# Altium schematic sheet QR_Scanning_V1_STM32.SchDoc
size 381 x 241 mm; SheetNumber: 1; SheetTotal: 3
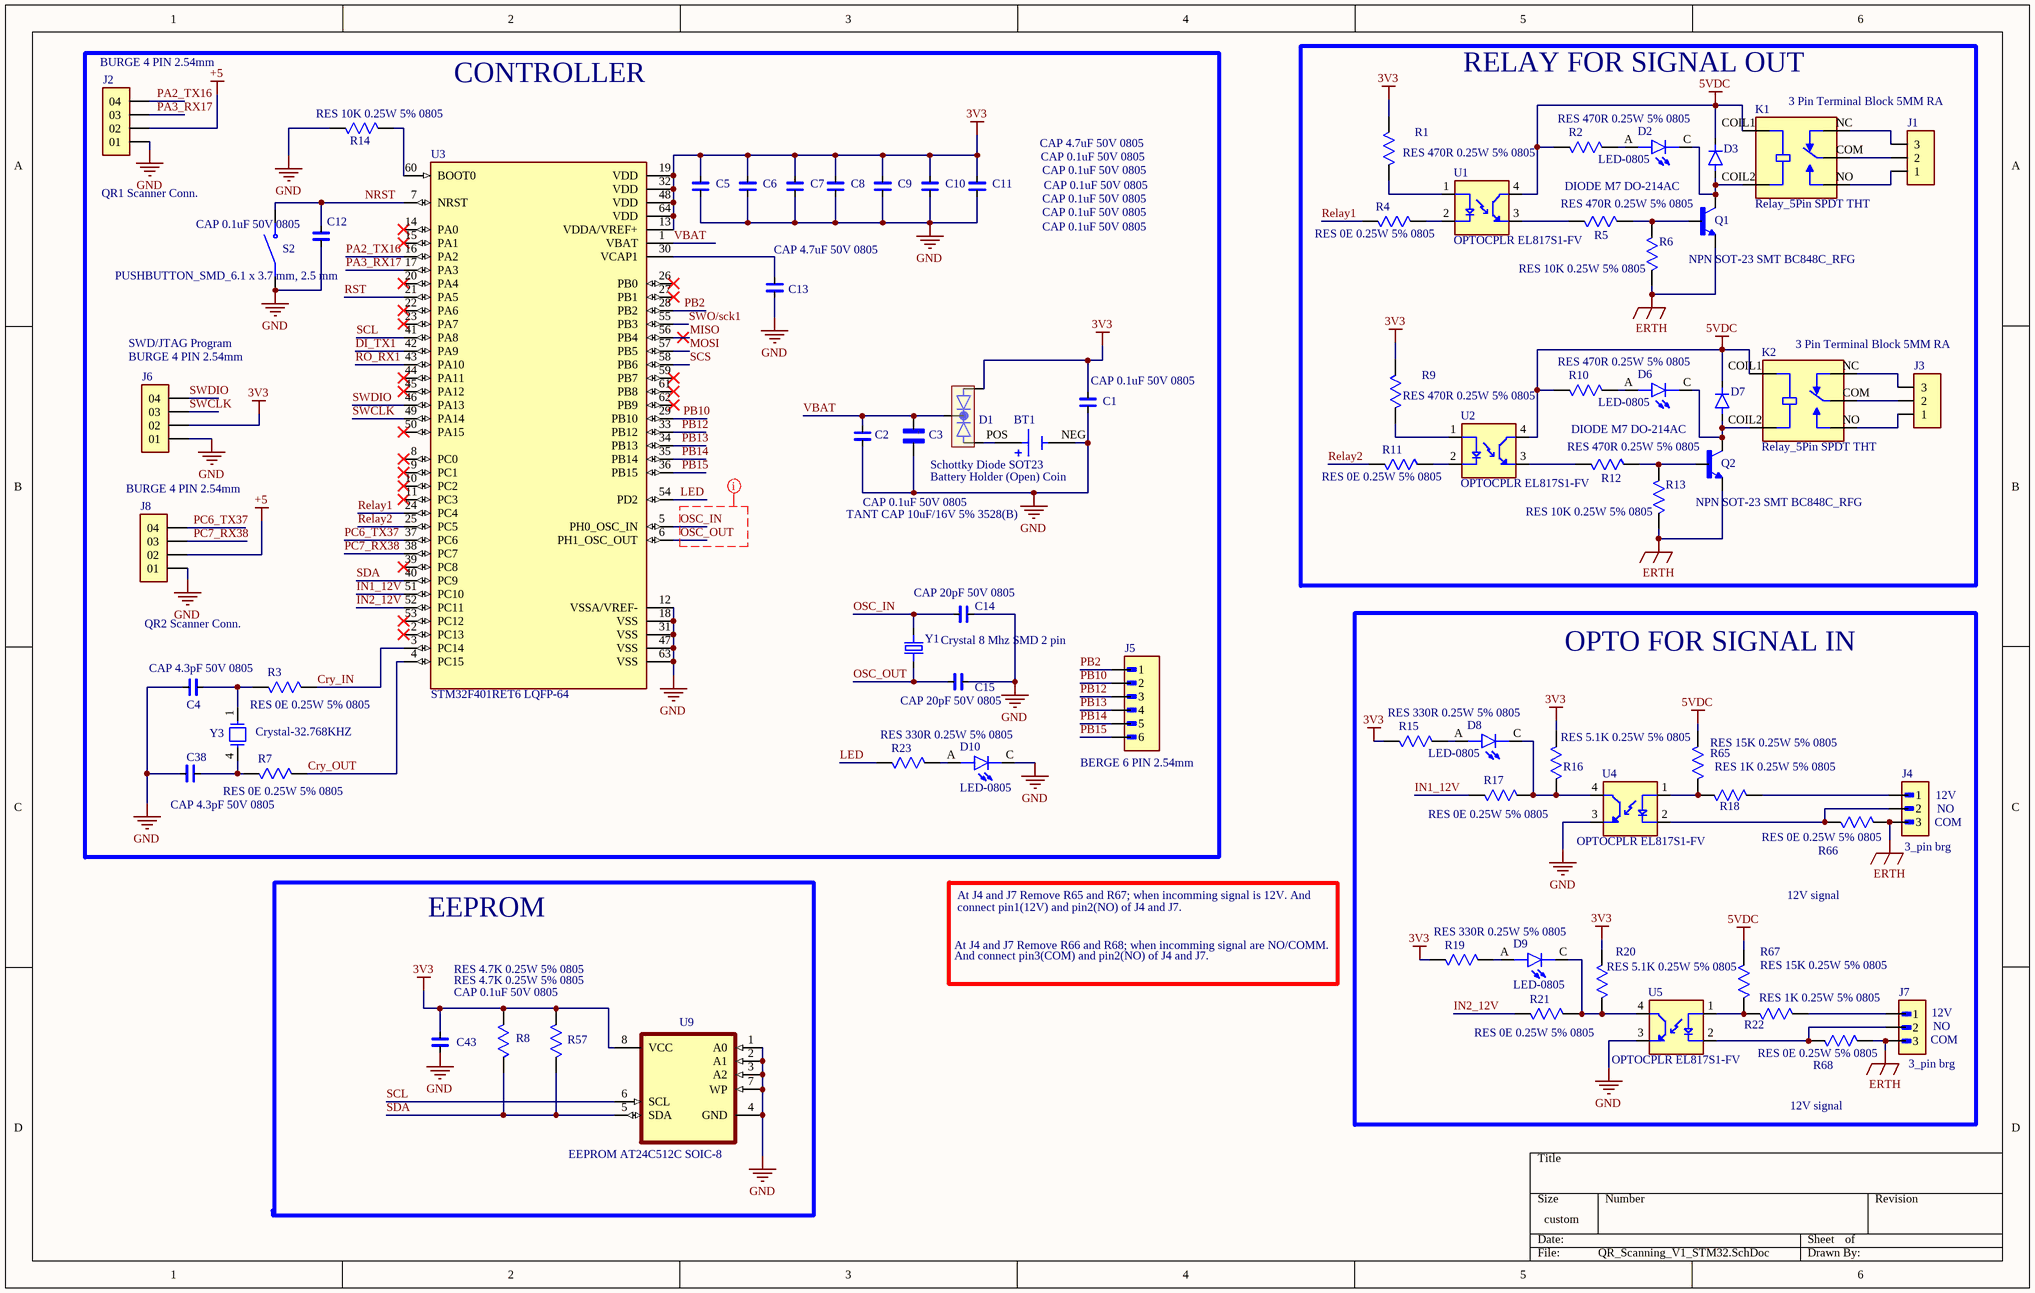
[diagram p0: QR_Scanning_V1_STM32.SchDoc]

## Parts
BT1  Battery Holder (Open) Coin  [Battery Holder (Open) Coin]
C1  CAP 0.1uF 50V 0805  [CAP CER 0.1uF/50V 5%]
C2  CAP 0.1uF 50V 0805  [CAP CER 0.1uF/50V 5%]
C3  TANT CAP 10uF/16V 5% 3528(B)  [TANT CAP 3528(B)]
C4  CAP 4.3pF 50V 0805  [CAP CER 0.1uF/50V 5%]
C5  CAP 0.1uF 50V 0805  [CAP CER 0.1uF/50V 5%]
C6  CAP 0.1uF 50V 0805  [CAP CER 0.1uF/50V 5%]
C7  CAP 0.1uF 50V 0805  [CAP CER 0.1uF/50V 5%]
C8  CAP 0.1uF 50V 0805  [CAP CER 0.1uF/50V 5%]
C9  CAP 0.1uF 50V 0805  [CAP CER 0.1uF/50V 5%]
C10  CAP 0.1uF 50V 0805  [CAP CER 0.1uF/50V 5%]
C11  CAP 4.7uF 50V 0805  [CAP CER 0.1uF/50V 5%]
C12  CAP 0.1uF 50V 0805  [CAP CER 0.1uF/50V 5%]
C13  CAP 4.7uF 50V 0805  [CAP CER 0.1uF/50V 5%]
C14  CAP 20pF 50V 0805  [CAP CER 0.1uF/50V 5%]
C15  CAP 20pF 50V 0805  [CAP CER 0.1uF/50V 5%]
C38  CAP 4.3pF 50V 0805  [CAP CER 0.1uF/50V 5%]
C43  CAP 0.1uF 50V 0805  [CAP CER 0.1uF/50V 5%]
D1  Schottky Diode SOT23  [Schottky Diode SOT23 BAT54C]
D2  LED-0805  [LED-0805]
D3  DIODE M7 DO-214AC  [DIODE M7 DO-214AC]
D6  LED-0805  [LED-0805]
D7  DIODE M7 DO-214AC  [DIODE M7 DO-214AC]
D8  LED-0805  [LED-0805]
D9  LED-0805  [LED-0805]
D10  LED-0805  [LED-0805]
J1  3 Pin Terminal Block 5MM RA  [3 Pin Terminal Block 5MM RA]
J2  BURGE 4 PIN 2.54mm  [BURGE 4 PIN 2.54mm]
J3  3 Pin Terminal Block 5MM RA  [3 Pin Terminal Block 5MM RA]
J4  3_pin brg  [3_pin brg]
J5  BERGE 6 PIN 2.54mm  [BERGE 6 PIN 2.54mm]
J6  BURGE 4 PIN 2.54mm  [BURGE 4 PIN 2.54mm]
J7  3_pin brg  [3_pin brg]
J8  BURGE 4 PIN 2.54mm  [BURGE 4 PIN 2.54mm]
K1  Relay_5Pin SPDT THT  [Relay_5Pin SPDT THT]
K2  Relay_5Pin SPDT THT  [Relay_5Pin SPDT THT]
Q1  NPN SOT-23 SMT BC848C_RFG  [NPN SOT-23 SMT BC848C_RFG]
Q2  NPN SOT-23 SMT BC848C_RFG  [NPN SOT-23 SMT BC848C_RFG]
R1  RES 470R 0.25W 5% 0805  [RES 0805 10K/0.25W 5%]
R2  RES 470R 0.25W 5% 0805  [RES 0805 10K/0.25W 5%]
R3  RES 0E 0.25W 5% 0805  [RES 0805 10K/0.25W 5%]
R4  RES 0E 0.25W 5% 0805  [RES 0805 10K/0.25W 5%]
R5  RES 470R 0.25W 5% 0805  [RES 0805 10K/0.25W 5%]
R6  RES 10K 0.25W 5% 0805  [RES 0805 10K/0.25W 5%]
R7  RES 0E 0.25W 5% 0805  [RES 0805 10K/0.25W 5%]
R8  RES 4.7K 0.25W 5% 0805  [RES 0805 10K/0.25W 5%]
R9  RES 470R 0.25W 5% 0805  [RES 0805 10K/0.25W 5%]
R10  RES 470R 0.25W 5% 0805  [RES 0805 10K/0.25W 5%]
R11  RES 0E 0.25W 5% 0805  [RES 0805 10K/0.25W 5%]
R12  RES 470R 0.25W 5% 0805  [RES 0805 10K/0.25W 5%]
R13  RES 10K 0.25W 5% 0805  [RES 0805 10K/0.25W 5%]
R14  RES 10K 0.25W 5% 0805  [RES 0805 10K/0.25W 5%]
R15  RES 330R 0.25W 5% 0805  [RES 0805 10K/0.25W 5%]
R16  RES 5.1K 0.25W 5% 0805  [RES 0805 10K/0.25W 5%]
R17  RES 0E 0.25W 5% 0805  [RES 0805 10K/0.25W 5%]
R18  RES 1K 0.25W 5% 0805  [RES 0805 10K/0.25W 5%]
R19  RES 330R 0.25W 5% 0805  [RES 0805 10K/0.25W 5%]
R20  RES 5.1K 0.25W 5% 0805  [RES 0805 10K/0.25W 5%]
R21  RES 0E 0.25W 5% 0805  [RES 0805 10K/0.25W 5%]
R22  RES 1K 0.25W 5% 0805  [RES 0805 10K/0.25W 5%]
R23  RES 330R 0.25W 5% 0805  [RES 0805 10K/0.25W 5%]
R57  RES 4.7K 0.25W 5% 0805  [RES 0805 10K/0.25W 5%]
R65  RES 15K 0.25W 5% 0805  [RES 0805 10K/0.25W 5%]
R66  RES 0E 0.25W 5% 0805  [RES 0805 10K/0.25W 5%]
R67  RES 15K 0.25W 5% 0805  [RES 0805 10K/0.25W 5%]
R68  RES 0E 0.25W 5% 0805  [RES 0805 10K/0.25W 5%]
S2  PUSHBUTTON_SMD_6.1 x 3.7 mm, 2.5 mm  [PUSHBUTTON_SMD_6.1 x 3.7 mm, 2.5 mm]
U1  OPTOCPLR EL817S1-FV  [OPTOCPLR EL817S1-FV]
U2  OPTOCPLR EL817S1-FV  [OPTOCPLR EL817S1-FV]
U3  STM32F401RET6 LQFP-64  [STM32F401RE Cortex-M4]
U4  OPTOCPLR EL817S1-FV  [OPTOCPLR EL817S1-FV]
U5  OPTOCPLR EL817S1-FV  [OPTOCPLR EL817S1-FV]
U9  EEPROM AT24C512C SOIC-8  [EEPROM AT24C512C SOIC-8]
Y1  Crystal 8 Mhz SMD 2 pin  [Crystal 16 Mhz SMD 2 pin]
Y3  Crystal-32.768KHZ  [Crystal-32.768KHZ]

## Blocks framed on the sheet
CONTROLLER: BT1 C1-C15 C38 D1 D10 J2 J5 J6 J8 R3 R7 R14 R23 S2 U3 Y1 Y3
RELAY FOR SIGNAL OUT: D2 D3 D6 D7 J1 J3 K1 K2 Q1 Q2 R1 R2 R4-R6 R9-R13 U1 U2
OPTO FOR SIGNAL IN: D8 D9 J4 J7 R15-R22 R65-R68 U4 U5

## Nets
3V3: C1.2 C5.2 C6.2 C7.2 C8.2 C9.2 C10.2 C11.2 C43.2 D1.1(A1) J6.02 R1.2 R8.2 R9.2 R15.2 R16.1 R19.2 R20.1 R57.2 U3.13(VDDA/VREF+) U3.19(VDD) U3.32(VDD) U3.48(VDD) U3.64(VDD) U9.8(VCC)
5VDC: D3.C(K) D7.C(K) K1.COIL1 K2.COIL1 R2.2 R10.2 R65.1 R67.1 U1.4(CT) U2.4(CT)
+5: J2.02 J8.02
ERTH: J4.3 J7.3 Q1.2(E) Q2.2(E) R6.1 R13.1 R66.1 R68.1
GND: BT1.NEG C1.1 C2.1 C3.2 C4.2 C5.1 C6.1 C7.1 C8.1 C9.1 C10.1 C11.1 C12.1 C13.1 C14.2 C15.2 C38.2 C43.1 D10.C J2.01 J6.01 J8.01 R14.1 S2.1 U3.12(VSSA/VREF-) U3.18(VSS) U3.31(VSS) U3.47(VSS) U3.63(VSS) U4.3(ET) U5.3(ET) U9.1(A0) U9.2(A1) U9.3(A2) U9.4(GND) U9.7(WP)
Cry_IN: R3.1 U3.3(PC14)
Cry_OUT: R7.1 U3.4(PC15)
DI_TX1: U3.42(PA9)
IN1_12V: R17.2 U3.51(PC10)
IN2_12V: R21.2 U3.52(PC11)
LED: R23.2 U3.54(PD2)
MISO: U3.56(PB4)
MOSI: U3.57(PB5)
NRST: C12.2 S2.2 U3.7(NRST)
OSC_IN: C14.1 U3.5(PH0_OSC_IN) Y1.2
OSC_OUT: C15.1 U3.6(PH1_OSC_OUT) Y1.1
PA2_TX16: J2.04 U3.16(PA2)
PA3_RX17: J2.03 U3.17(PA3)
PB2: J5.1 U3.28(PB2)
PB10: J5.2 U3.29(PB10)
PB12: J5.3 U3.33(PB12)
PB13: J5.4 U3.34(PB13)
PB14: J5.5 U3.35(PB14)
PB15: J5.6 U3.36(PB15)
PC6_TX37: J8.04 U3.37(PC6)
PC7_RX38: J8.03 U3.38(PC7)
Relay1: R4.2 U3.24(PC4)
Relay2: R11.2 U3.25(PC5)
RO_RX1: U3.43(PA10)
RST: U3.21(PA5)
SCL: U3.41(PA8) U9.6(SCL)
SCS: U3.58(PB6)
SDA: R8.1 R57.1 U3.40(PC9) U9.5(SDA)
SWCLK: J6.03 U3.49(PA14)
SWDIO: J6.04 U3.46(PA13)
SWO/sck1: U3.55(PB3)
VBAT: C2.2 C3.1 D1.3(C) U3.1(VBAT)
NetBT1_POS: BT1.POS D1.2(A2)
NetC4_1: C4.1 R3.2 Y3.1
NetC13_2: C13.2 U3.30(VCAP1)
NetC38_1: C38.1 R7.2 Y3.4
NetD2_A: D2.A R2.1
NetD2_C: D2.C D3.A K1.COIL2 Q1.3(C)
NetD6_A: D6.A R10.1
NetD6_C: D6.C D7.A K2.COIL2 Q2.3(C)
NetD8_A: D8.A R15.1
NetD8_C: D8.C R16.2 R17.1 U4.4(CT)
NetD9_A: D9.A R19.1
NetD9_C: D9.C R20.2 R21.1 U5.4(CT)
NetD10_A: D10.A R23.1
NetJ1_1: J1.1 K1.NO
NetJ1_2: J1.2 K1.COM
NetJ1_3: J1.3 K1.NC
NetJ3_1: J3.1 K2.NO
NetJ3_2: J3.2 K2.COM
NetJ3_3: J3.3 K2.NC
NetJ4_1: J4.1 R18.1
NetJ4_2: J4.2 R66.2 U4.2(C)
NetJ7_1: J7.1 R22.1
NetJ7_2: J7.2 R68.2 U5.2(C)
NetQ1_1: Q1.1(B) R5.2 R6.2
NetQ2_1: Q2.1(B) R12.2 R13.2
NetR1_1: R1.1 U1.1(A)
NetR4_1: R4.1 U1.2(C)
NetR5_1: R5.1 U1.3(ET)
NetR9_1: R9.1 U2.1(A)
NetR11_1: R11.1 U2.2(C)
NetR12_1: R12.1 U2.3(ET)
NetR14_2: R14.2 U3.60(BOOT0)
NetR18_2: R18.2 R65.2 U4.1(A)
NetR22_2: R22.2 R67.2 U5.1(A)

Not connected (* = marked no-connect by the designer): U3 2(PC13)* 8(PC0)* 9(PC1)* 10(PC2)* 11(PC3)* 14(PA0)* 15(PA1)* 20(PA4)* 22(PA6)* 23(PA7)* 26(PB0)* 27(PB1)* 39(PC8)* 44(PA11)* 45(PA12)* 50(PA15)* 53(PC12)* 59(PB7)* 61(PB8)* 62(PB9)*

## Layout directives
net class Single_50 ohm: OSC_IN, OSC_OUT

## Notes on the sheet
- (near J2) QR1 Scanner Conn.
- (near J6) SWD/JTAG Program
- QR2 Scanner Conn.
- (near J4) COM
- (near J4) 12V
- (near J4) NO
- At J4 and J7 Remove R65 and R67; when incomming signal is 12V. And
- connect pin1(12V) and pin2(NO) of J4 and J7.
- 12V signal
- EEPROM
- At J4 and J7 Remove R66 and R68; when incomming signal are NO/COMM.
- And connect pin3(COM) and pin2(NO) of J4 and J7.
- (near J7) COM
- (near J7) 12V
- (near J7) NO

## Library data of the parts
BT1 = Battery Holder (Open) Coin: Battery Holder (Open) Coin, 20.0mm 1 Cell SMD (SMT) Tab, CR2032, BS-7-RED
C1 C2 C4-C15 C38 C43 = CAP CER 0.1uF/50V 5%: CAP CER 0.1uF/50V  Ceramic Capacitor X7R 0805 (2012 Metric) SMT; MF: Samsung; MP: CL21B104KCFNNNE
C3 = TANT CAP 10uF/16V 5% 3528(B): 10 ÂµF Molded Tantalum Polymer Capacitor 25 V 1411 (3528 Metric), 1210 150mOhm TCJB106M025R0150; MF: AVX
D1 = Schottky Diode SOT23 BAT54C: Schottky Diode 2x ComCath 0.2A 30V SOT23 ¦ Diodes Inc BAT54C; MF: Diodes Inc.; MP: BAT54C-7-F
D2 D6 D8-D10 = LED-0805: Red 640nm LED Indication - Discrete 1.85V 0805 (2012 Metric) APT2012SRCPRV; MF: Kingbright
D3 D7 = DIODE M7 DO-214AC: M7 General Purpose SMD Rectifier Diode SMA (DO-214AC) 1A 1000V 1n4007 RS2MA; MF: Taiwan Semiconductor
J1 J3 = 3 Pin Terminal Block 5MM RA: 3 Pin Terminal Block HDR 5MM THT RA 231-433_001-000; MP: 231-433/001-000; MF: WAGO
J2 J6 J8 = BURGE 4 PIN 2.54mm: Conn Unshrouded Header HDR 4 POS 2.54mm Solder ST Top Entry Thru-Hole Bulk TSW-104-17-G-S-LL; MF: Samtec; MP: TSW-104-23-H-S-LL
J4 J7 = 3_pin brg: 3_pin burge 2.54mm; MP: 68001-403HLF
J5 = BERGE 6 PIN 2.54mm: BergStik, Board to Board connector, Unshrouded Vertical Header, Through Hole, Single Row, 6 Positions, 2.54 mm (0.100in) Pitch. 68604-406HLF; MF: AMPHENOL ICC / FCI
K1 K2 = Relay_5Pin SPDT THT: Relays General Purpose Non Latching 3VDC SPDT 10A (250VAC) Max 5PIN SRD-03VDC-SL-C; MF: Songle Relay
Q1 Q2 = NPN SOT-23 SMT BC848C_RFG: NPN SMT BC848C_RFG SOT-23, 30V, 0.1A, NPN Transistor; MF: Taiwan Semiconductor; MP: BC848C RFG
R1-R23 R57 R65-R68 = RES 10K 0.25W 5% 0805: RESISTOR, THICK FILM, 10K, 5%, 0805 0.25W SMT; MP: ERJ-6GEYJ103V; MF: Panasonic Electronic
S2 = PUSHBUTTON_SMD_6.1 x 3.7 mm, 2.5 mm: 6.1 x 3.7 mm, 2.5 mm Actuator Height, 260 gf, Red, Surface Mount, SPST, Tactile Switch, TS09-63-25-R-260-SMT-TR; MF: Same Sky
U1 U2 U4 U5 = Optclr EL817S1-FV: Optoisoltr 5kv Transistor 4-Smd EL817S1-FV; MF: {'manufacturer': u'Everlight Electronics Co Ltd'}; MP: EL817S1(A)(TU)-V
U3 = STM32F401RET6: ARMÂ® CortexÂ®-M4 STM32F4 Microcontroller IC 32-Bit Single-Core 84MHz 512KB (512K x 8) FLASH 64-LQFP (10x10); MF: STMicroelectronics
U9 = EEPROM AT24C512C SOIC-8: EEPROM Memory IC 512Kb (64K x 8) IÂ²C 400 kHz 900 ns SOIC-8 AT24C512C-SSHM-T; MF: Microchip
Y1 = Crystal 16 Mhz SMD 2 pin_1: 16 MHz Â±30ppm Crystal 20pF 60 Ohms HC-49/US FOXSDLF/128-20 16 Mhz Crystal SMD –CSM-4ALX(28ALX) 12.5mmX4.85mmX4mm; MF: Fox Electronics
Y3 = Crystal-32.768KHZ: 32.768 kHz Â±20ppm Crystal 6pF 50 kOhms 4-SOJ, 5.50mm pitch ABS25-32.768KHZ-6-T; MF: Abracon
